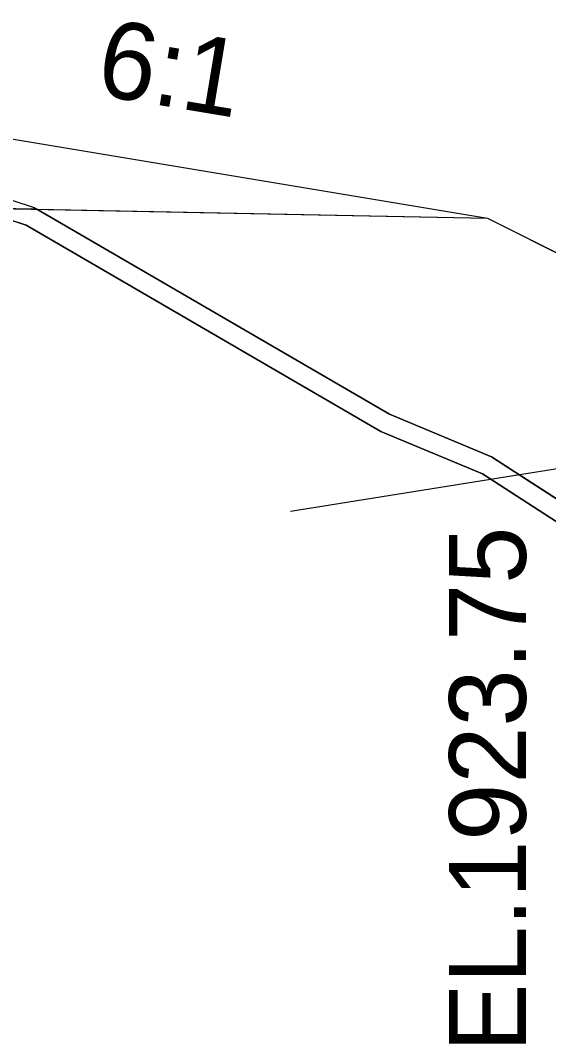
# Model space of a CAD drawing. Extents: x 1574 to 14903, y 7971 to 16537.
# Drawn here: x 14623.78 to 14630.67, y 9006 to 9019.32 of the extents above; entities that cross this region are included whole.
import ezdxf

# ---------------------------------------------------------------- set-up
doc = ezdxf.new("R2010")
doc.units = 0
for name, color, linetype in [('DESIGN - EARTHWORK - Shapes', 7, 'Continuous'), ('DESIGN - SCRATCH - User 1', 7, 'Continuous'), ('DESIGN - TYPICAL - Finished Grade and Subgrade', 7, 'Continuous'), ('DESIGN - TYPICAL - Finished Grade Slopes Text', 7, 'Continuous'), ('DESIGN - TYPICAL - Slope Tie Text', 7, 'Continuous'), ('DESIGN - TYPICAL - Subgrade Tie Text', 7, 'Continuous'), ('SURVEY - GROUND - Bottom of Topsoil Layer', 7, 'Continuous'), ('SURVEY - GROUND - Top of Ground', 7, 'Continuous')]:
    doc.layers.add(name, color=color, linetype=linetype)

msp = doc.modelspace()

# ---------------------------------------------------------------- linework, layer by layer
at = {"layer": 'DESIGN - EARTHWORK - Shapes'}
for points in [[(14614.486, 9019.046), (14614.486, 9019.046), (14614.486, 9019.297), (14616.713, 9019.128), (14617.25, 9019.087), (14617.929, 9018.918), (14618.449, 9018.693), (14623.96, 9016.884), (14623.997, 9016.862), (14623.174, 9016.879), (14618.36, 9018.459), (14617.849, 9018.68), (14617.21, 9018.84), (14616.694, 9018.878), (14614.486, 9019.046), (14614.486, 9019.046)], [(14623.174, 9016.879), (14623.997, 9016.862), (14628.592, 9014.192), (14629.924, 9013.639), (14633.692, 9011.203), (14634.21, 9010.814), (14636.05, 9010.617), (14638.68, 9010.23), (14640.45, 9010.159), (14643.267, 9010.047), (14643.267, 9009.797), (14638.657, 9009.981), (14636.019, 9010.369), (14634.114, 9010.572), (14633.548, 9010.998), (14629.807, 9013.417), (14628.48, 9013.967), (14623.857, 9016.654)], [(14629.871, 9016.745), (14643.267, 9010.047), (14641.73, 9010.108), (14640.45, 9010.159), (14638.68, 9010.23), (14636.05, 9010.617), (14634.21, 9010.814), (14633.692, 9011.203), (14629.924, 9013.639), (14628.592, 9014.192), (14623.997, 9016.862)]]:
    msp.add_lwpolyline(points, close=True, dxfattribs=at)
at = {"layer": 'DESIGN - SCRATCH - User 1'}
msp.add_lwpolyline([(14637.36, 9013), (14630.912, 9013), (14629.924, 9013.639), (14628.592, 9014.192), (14628.263, 9014.383)], dxfattribs=at)
at = {"layer": 'DESIGN - TYPICAL - Finished Grade and Subgrade'}
for p, q in [((14622, 9018.057), (14629.871, 9016.745)), ((14609.339, 9017.155), (14629.871, 9016.745)), ((14629.871, 9016.745), (14637.36, 9013))]:
    msp.add_line(p, q, dxfattribs=at)
at = {"layer": 'DESIGN - TYPICAL - Slope Tie Text'}
msp.add_lwpolyline([(14627.301, 9012.931), (14633.226, 9013.878), (14634.46, 9013)], dxfattribs=at)
at = {"layer": 'SURVEY - GROUND - Bottom of Topsoil Layer'}
msp.add_lwpolyline([(14614.486, 9019.046), (14616.694, 9018.878), (14617.21, 9018.84), (14617.849, 9018.68), (14618.36, 9018.459), (14623.857, 9016.654), (14628.48, 9013.967), (14629.807, 9013.417), (14633.548, 9010.998), (14634.114, 9010.572), (14636.019, 9010.369), (14638.657, 9009.981), (14647.085, 9009.644), (14648.633, 9009.477), (14651.028, 9009.503), (14654.654, 9010.61)], dxfattribs=at)
at = {"layer": 'SURVEY - GROUND - Top of Ground'}
msp.add_lwpolyline([(14618.449, 9018.693), (14623.96, 9016.884), (14628.592, 9014.192), (14629.924, 9013.639), (14633.692, 9011.203), (14634.21, 9010.814), (14636.05, 9010.617), (14638.68, 9010.23), (14647.103, 9009.894), (14648.646, 9009.727), (14650.989, 9009.753), (14654.594, 9010.854)], dxfattribs=at)
msp.add_lwpolyline([(14618.449, 9018.693), (14623.96, 9016.884), (14628.592, 9014.192), (14629.924, 9013.639), (14633.692, 9011.203), (14634.21, 9010.814), (14636.05, 9010.617), (14638.68, 9010.23), (14647.103, 9009.894), (14648.646, 9009.727), (14650.989, 9009.753), (14654.594, 9010.854)], dxfattribs=at)

# ---------------------------------------------------------------- texts
at = {"layer": 'DESIGN - TYPICAL - Finished Grade Slopes Text'}
msp.add_text('6:1', height=1, rotation=350.5377, dxfattribs=at).set_placement((14624.744, 9018.36))
at = {"layer": 'DESIGN - TYPICAL - Subgrade Tie Text'}
msp.add_text('EL.1923.75', height=1, rotation=90, dxfattribs=at).set_placement((14630.371, 9005.888))

doc.saveas('drawing.dxf')
